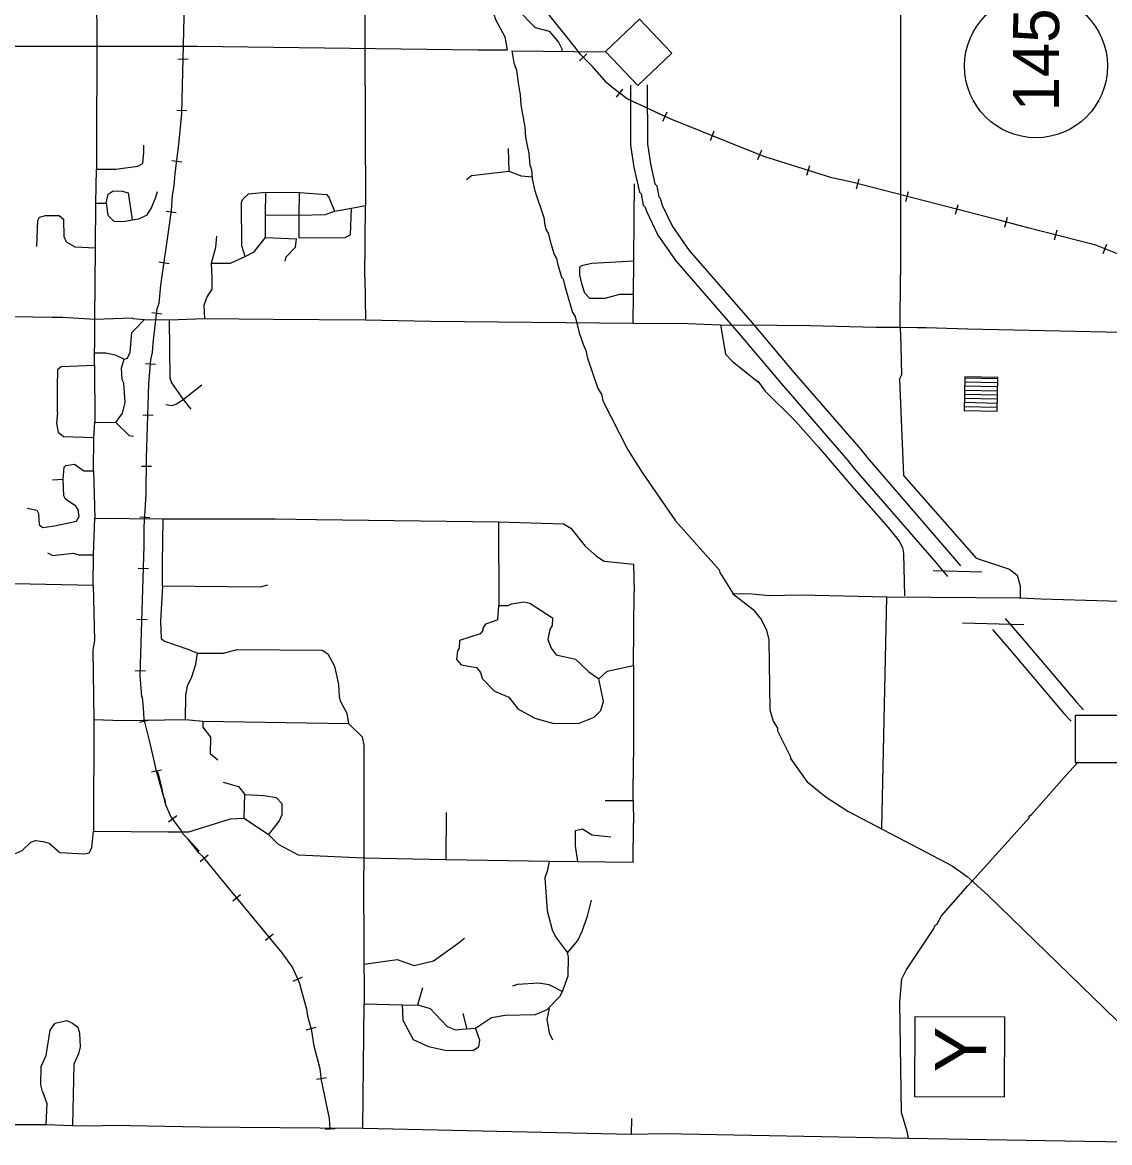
# Model space of a CAD drawing. Extents: x 299354 to 1325680, y 96128 to 228242.
# Drawn here: x 350586 to 371846, y 99941 to 121836 of the extents above; entities that cross this region are included whole.
import ezdxf

# ---------------------------------------------------------------- set-up
doc = ezdxf.new("R2010")
doc.units = 0
for name, color, linetype in [('Level 10', 7, 'Continuous'), ('Level 12', 7, 'Continuous'), ('Level 13', 7, 'Continuous'), ('Level 2', 7, 'Continuous'), ('Level 3', 7, 'Continuous'), ('Level 4', 7, 'Continuous'), ('Level 51', 7, 'Continuous')]:
    doc.layers.add(name, color=color, linetype=linetype)

msp = doc.modelspace()

# ---------------------------------------------------------------- linework, layer by layer
at = {"layer": 'Level 10'}
for p, q in [((368405, 111124), (369350, 111099)), ((368969, 110098), (370168, 110065))]:
    msp.add_line(p, q, dxfattribs=at)
msp.add_lwpolyline([(370086, 110590), (370094, 110590)], dxfattribs=at)
at = {"layer": 'Level 12'}
msp.add_line((370406, 120980), (370406, 120980), dxfattribs=at)
msp.add_circle((370406, 120980), 1398, dxfattribs=at)
at = {"layer": 'Level 13'}
msp.add_line((368892, 101648), (368892, 101648), dxfattribs=at)
msp.add_lwpolyline([(369786, 100826), (368036, 100833), (368042, 102403), (369792, 102396)], close=True, dxfattribs=at)
at = {"layer": 'Level 2'}
for points in [[(367755, 123819), (367758, 116894)], [(359766, 122050), (359807, 122000), (359840, 121891), (360020, 121556), (360068, 121297)], [(329011, 121428), (334049, 121433), (334274, 121464), (334492, 121579), (334660, 121736), (334853, 121834), (334986, 121833), (335377, 121696), (335951, 121566), (336410, 121528), (349544, 121393), (349810, 121323), (350219, 121370), (353997, 121369)], [(353997, 121369), (359492, 121302), (360068, 121297)], [(360159, 121280), (360199, 121046), (360248, 120904), (360279, 120654), (360318, 120420), (360333, 120228), (360412, 119786), (360427, 119586), (360491, 119277), (360506, 119043), (360538, 118960), (360553, 118784), (360601, 118567), (360780, 118024), (360803, 117874), (360819, 117790), (360869, 117715), (360917, 117514), (360982, 117297), (361031, 117222), (361047, 117122), (361128, 116854), (361161, 116821), (361193, 116679), (361346, 116169), (361396, 116085), (361476, 115768), (361557, 115525), (361606, 115425), (361638, 115275), (361841, 114681), (361907, 114572), (361939, 114438), (362423, 113484), (362702, 113040), (363360, 112092), (364211, 111134), (364227, 111084), (364486, 110666)], [(360159, 121280), (361991, 121263)], [(362475, 120612), (362479, 119436), (362545, 119010), (362652, 118516), (362683, 118484), (362723, 118267), (362763, 118227), (362787, 118145), (363011, 117678), (363361, 117173), (364604, 115747), (365429, 114773), (365562, 114621), (366730, 113273), (366846, 113122), (367839, 111976), (368408, 111322), (368675, 111003)], [(362805, 120613), (362809, 119462), (362870, 119070), (362955, 118679), (362990, 118643), (363029, 118426), (363056, 118399), (363096, 118264), (363297, 117844), (363622, 117376), (364855, 115962), (365680, 114988), (365811, 114838), (366986, 113481), (367102, 113330), (368089, 112192), (368659, 111536), (368928, 111215)], [(367749, 115878), (367758, 116894)], [(367749, 115878), (367762, 115519)], [(367762, 115519), (367774, 114944)], [(367739, 114861), (367774, 114944)], [(367739, 114861), (367815, 112981)], [(367815, 112981), (369237, 111362)], [(369237, 111362), (369890, 111150), (370039, 111032), (370096, 110823), (370094, 110590)], [(368400, 111121), (368406, 111114)], [(364473, 110676), (364879, 110362), (365036, 110160), (365134, 109959), (365182, 109767), (365203, 108400), (365268, 108175), (365350, 108041), (365349, 107991), (365603, 107480), (365603, 107447), (365924, 107002), (366305, 106690), (366727, 106420), (368246, 105623), (368769, 105351), (369059, 105140), (369473, 104770), (371977, 102339), (372903, 101480), (373913, 100580), (374045, 100453), (374683, 99957)], [(369806, 110183), (370169, 109764), (371206, 108540), (371335, 108401)], [(369556, 109967), (369918, 109549), (370959, 108321), (371092, 108177)], [(367911, 100026), (367887, 100159), (367774, 100527), (367744, 102686), (367781, 103144), (367866, 103309), (368399, 104113), (368433, 104188), (368467, 104204), (368560, 104370), (369074, 104957), (369142, 105040), (370271, 106288), (370271, 106321), (370321, 106354), (371055, 107189), (371233, 107374)], [(349316, 100294), (351042, 100295)], [(351042, 100295), (351567, 100274)], [(351959, 100270), (352351, 100283)], [(352351, 100283), (354061, 100251)], [(351567, 100274), (351959, 100270)], [(354061, 100251), (356412, 100230)], [(356412, 100230), (357246, 100222)], [(357246, 100222), (362499, 100108)], [(362499, 100108), (363142, 100119)], [(363142, 100119), (367911, 100026)], [(367911, 100026), (371363, 99969)], [(371363, 99969), (373010, 99941)]]:
    msp.add_lwpolyline(points, dxfattribs=at)
for points in [[(361986, 121266), (362622, 120602), (363285, 121238), (362650, 121901)], [(371171, 107371), (372091, 107367), (372094, 108286), (371175, 108290)]]:
    msp.add_lwpolyline(points, close=True, dxfattribs=at)
at = {"layer": 'Level 3'}
for points in [[(362529, 115958), (363596, 115948), (364238, 115926)], [(364238, 115926), (365339, 115916), (365989, 115910)], [(365989, 115910), (367274, 115882)], [(367274, 115882), (367749, 115878)], [(367749, 115878), (368074, 115875)], [(368074, 115875), (368258, 115873)], [(368258, 115873), (369076, 115849)], [(369066, 115849), (372985, 115763)]]:
    msp.add_lwpolyline(points, dxfattribs=at)
at = {"layer": 'Level 4'}
for p, q in [((353628, 121122), (353828, 121117)), ((361483, 121085), (361626, 121225)), ((362204, 120375), (362325, 120534)), ((353603, 120122), (353803, 120117)), ((363109, 119909), (363193, 120090)), ((364040, 119530), (364114, 119715)), ((364968, 119158), (365042, 119344)), ((353505, 119137), (353704, 119112)), ((365927, 118849), (365987, 119040)), ((366896, 118585), (366946, 118779)), ((367864, 118335), (367914, 118529)), ((368833, 118085), (368883, 118279)), ((353398, 118145), (353596, 118118)), ((369800, 117835), (369851, 118028)), ((370770, 117585), (370819, 117779)), ((371717, 117318), (371793, 117503)), ((353257, 117156), (353454, 117127)), ((353114, 116165), (353313, 116141)), ((352992, 115170), (353191, 115154)), ((352941, 114167), (353141, 114161)), ((352912, 113165), (353112, 113163)), ((352880, 112171), (353079, 112159)), ((352852, 111169), (353052, 111163)), ((367393, 106087), (367490, 110611)), ((367490, 110611), (370094, 110590)), ((352823, 110169), (353023, 110163)), ((352794, 109170), (352994, 109164)), ((352879, 108156), (353073, 108204)), ((353108, 107186), (353304, 107228)), ((353443, 106212), (353603, 106332)), ((354062, 105437), (354217, 105564)), ((354699, 104666), (354853, 104793)), ((355337, 103896), (355491, 104024)), ((355884, 103095), (356065, 103180)), ((356136, 102147), (356329, 102200)), ((356334, 101181), (356532, 101210)), ((356504, 100204), (356704, 100219))]:
    msp.add_line(p, q, dxfattribs=at)
for points in [[(357266, 124535), (357296, 118256)], [(359708, 123009), (359945, 122432), (360259, 122096), (360614, 121734), (360888, 121665), (361070, 121447), (361136, 121321), (361135, 121271)], [(352015, 122537), (352041, 121828), (352032, 118970)], [(356604, 100211), (356589, 100411), (356438, 101163), (356406, 101380), (356294, 101823), (356246, 102123), (356166, 102415), (356150, 102549), (356053, 102891), (356013, 103042), (355988, 103109), (355866, 103368), (355668, 103653), (354464, 105106), (354126, 105517), (354043, 105601), (353821, 105878), (353722, 105979), (353705, 106029), (353491, 106315), (353393, 106541), (353353, 106691), (353207, 107201), (353143, 107493), (353063, 107827), (352967, 108219), (352952, 108436), (352937, 108645), (352921, 108653), (352891, 109070), (352915, 109912), (352964, 111603), (352968, 111978), (353007, 112619), (353014, 113319), (353060, 114777), (353098, 115243), (353133, 115385), (353143, 115568), (353224, 116242), (353258, 116350), (353295, 116700), (353331, 116975), (353438, 117699), (353500, 118157), (353520, 118448), (353555, 118648), (353574, 118881), (353646, 119447), (353701, 120055), (353755, 122204)], [(353574, 118881), (353646, 119447), (353701, 120055), (353755, 122204)], [(362411, 120343), (362113, 120570), (362013, 120655), (361725, 120982), (361493, 121218), (361411, 121335), (360801, 122091), (360570, 122359)], [(362591, 120259), (362411, 120343), (362113, 120570), (362013, 120655), (361725, 120982), (361493, 121218), (361411, 121335), (360801, 122091)], [(363254, 119952), (362411, 120343)], [(372032, 117297), (371575, 117485), (370244, 117822), (369686, 117968), (366808, 118711), (366414, 118800), (365086, 119218), (363254, 119952), (362941, 120097)], [(366414, 118800), (365086, 119218), (363254, 119952)], [(352032, 118970), (352415, 118966), (352841, 119029), (352942, 119078), (352960, 119295), (352962, 119437)], [(360083, 119372), (360096, 118930)], [(352025, 118303), (352032, 118970)], [(359269, 118763), (359370, 118845), (360096, 118930)], [(360096, 118930), (360337, 118836), (360554, 118818)], [(353143, 115568), (353224, 116242), (353258, 116350), (353295, 116700), (353331, 116975), (353438, 117699), (353500, 118157), (353520, 118448), (353555, 118648), (353574, 118881)], [(362548, 118008), (362554, 118683)], [(369686, 117968), (366808, 118711), (366414, 118800)], [(352226, 118301), (352261, 118476), (352361, 118542), (352536, 118540), (352653, 118506), (352731, 117980)], [(352731, 117980), (352865, 117996), (353024, 118078), (353109, 118210), (353194, 118418), (353229, 118534)], [(354943, 117260), (354878, 117469), (354870, 118328), (354904, 118386), (355005, 118485), (355347, 118515)], [(355343, 118073), (355347, 118515)], [(355347, 118515), (356006, 118509)], [(356001, 118067), (356006, 118509)], [(356006, 118509), (356531, 118471), (356580, 118420), (356686, 118144)], [(352017, 117428), (352025, 118303)], [(352025, 118303), (352226, 118301)], [(352226, 118301), (352257, 118068), (352373, 117950), (352564, 117948), (352731, 117980)], [(357020, 118208), (357296, 118256)], [(357283, 116856), (357296, 118256)], [(350867, 117455), (350888, 117964), (350922, 118030), (351039, 118062), (351306, 118060), (351389, 117992), (351394, 117651), (351443, 117550), (351609, 117449), (352017, 117428)], [(355339, 117632), (355343, 118073)], [(355343, 118073), (356001, 118067)], [(355997, 117626), (356898, 117634), (356999, 117683), (357020, 118208)], [(355997, 117626), (356001, 118067)], [(356001, 118067), (356510, 118079), (356686, 118144)], [(356686, 118144), (357020, 118208)], [(362540, 117175), (362548, 118008)], [(371575, 117485), (370244, 117822), (369686, 117968)], [(354283, 117133), (354369, 117440), (354388, 117657)], [(354943, 117260), (355119, 117350), (355339, 117632)], [(355339, 117632), (355947, 117609)], [(355726, 117170), (355744, 117253), (355929, 117443), (355947, 117609)], [(352005, 116037), (352017, 117428)], [(375984, 115353), (375410, 115483), (374511, 115666), (374286, 115752), (373838, 115989), (373283, 116386), (372993, 116638), (372604, 116917), (372356, 117119), (372032, 117297), (371575, 117485)], [(354283, 117133), (354658, 117129), (354943, 117260)], [(362534, 116516), (362259, 116519), (361974, 116438), (361683, 116441), (361583, 116542), (361535, 116709), (361487, 116901), (361488, 117051), (361522, 117084), (361722, 117132), (362540, 117175)], [(362534, 116516), (362540, 117175)], [(354156, 116051), (354142, 116309), (354194, 116459), (354295, 116624), (354297, 116833), (354283, 117133)], [(357283, 116856), (357292, 116022)], [(362529, 115958), (362534, 116516)], [(346660, 116152), (351171, 116078), (351371, 116076)], [(351371, 116076), (352005, 116037)], [(352005, 116037), (352730, 116064), (352747, 116047), (352972, 116028)], [(353456, 116024), (354156, 116051)], [(354156, 116051), (355491, 116039)], [(352000, 115578), (352005, 116037)], [(352573, 115257), (352640, 115273), (352691, 115389), (352728, 115772), (352795, 115846), (352972, 116028)], [(352972, 116028), (353456, 116024)], [(353456, 116024), (353470, 114890), (353503, 114790), (353733, 114463)], [(355491, 116039), (357292, 116022)], [(357292, 116022), (358576, 115994)], [(358576, 115994), (362529, 115958)], [(364238, 115926), (364332, 115354), (364472, 115211), (364977, 114807)], [(351999, 115378), (352000, 115578)], [(352968, 111978), (353007, 112619), (353014, 113319), (353060, 114777), (353098, 115243), (353133, 115385), (353143, 115568)], [(351996, 115137), (351999, 115378)], [(351999, 115378), (352215, 115376), (352398, 115341), (352573, 115257)], [(352411, 114016), (352546, 114198), (352598, 114406), (352568, 114782), (352536, 114849), (352521, 115082), (352573, 115257)], [(351275, 114702), (351278, 115060), (351346, 115109), (351996, 115137)], [(351996, 115137), (352003, 114020)], [(353733, 114463), (354094, 114751)], [(364964, 114823), (365112, 114630)], [(351270, 114210), (351275, 114702)], [(365112, 114630), (365699, 114050), (366153, 113537), (366805, 112773), (367424, 112067), (367514, 111966), (367729, 111698), (367794, 111572), (367816, 111454)], [(353390, 114366), (353515, 114348), (353599, 114381), (353733, 114463)], [(353733, 114463), (353882, 114278)], [(351270, 114210), (351252, 113994), (351284, 113827), (351391, 113742), (351983, 113720)], [(351983, 113720), (352003, 114020)], [(352003, 114020), (352411, 114016)], [(352411, 114016), (352676, 113764), (352759, 113747)], [(351977, 113070), (351983, 113720)], [(351384, 112909), (351402, 113142), (351436, 113175), (351603, 113199), (351785, 113072), (351977, 113070)], [(351977, 113070), (352002, 112145)], [(350678, 112340), (350869, 112305), (350902, 112238), (350917, 112013), (350983, 111963), (351217, 111994), (351643, 112090), (351694, 112181), (351678, 112315), (351629, 112382), (351430, 112517), (351397, 112584), (351384, 112909)], [(351175, 112894), (351384, 112909)], [(351979, 111429), (352002, 112145)], [(352002, 112145), (353336, 112133)], [(353324, 110825), (353328, 111266), (353336, 112133)], [(353336, 112133), (355530, 112130)], [(355530, 112130), (356339, 112122)], [(356339, 112122), (359899, 112074)], [(352921, 108653), (352891, 109070), (352915, 109912), (352964, 111603), (352968, 111978)], [(359899, 112074), (359901, 110440)], [(359899, 112074), (361167, 112037), (361308, 111952), (361588, 111600)], [(351078, 111470), (351178, 111419), (351353, 111434), (351587, 111465), (351687, 111431), (351979, 111429)], [(361588, 111600), (361811, 111406)], [(367816, 111454), (367834, 110627)], [(351973, 110837), (351979, 111429)], [(361811, 111406), (361960, 111305), (362535, 111250)], [(362535, 111250), (362547, 110708)], [(349188, 110895), (351973, 110837)], [(351973, 110837), (351997, 109753), (351962, 109570), (351982, 108212)], [(353324, 110825), (353284, 110133), (353298, 109792), (353364, 109741), (353822, 109587), (354013, 109510)], [(353324, 110825), (355242, 110807), (355388, 110842)], [(362534, 109266), (362547, 110708)], [(364483, 110676), (364849, 110670)], [(364849, 110670), (365193, 110634)], [(365190, 110634), (365799, 110645)], [(365799, 110645), (367490, 110611)], [(370094, 110590), (370510, 110569), (371378, 110545)], [(359882, 110157), (359901, 110440)], [(359901, 110440), (360084, 110438), (360151, 110471), (360394, 110511), (360510, 110485), (360949, 110197), (360948, 110047), (360897, 109973), (360862, 109773), (360927, 109606), (361026, 109472), (361401, 109393), (361665, 109141), (361856, 109006)], [(371378, 110545), (372278, 110520)], [(359882, 110157), (359639, 110076), (359588, 109993), (359588, 109951), (359537, 109885), (359136, 109755), (359126, 109605), (359092, 109556), (359074, 109381), (359165, 109280), (359464, 109227), (359547, 109127), (359579, 109010), (359819, 108766), (360101, 108647), (360274, 108420), (360606, 108234), (360980, 108130), (361473, 108142), (361766, 108257), (361900, 108389), (361952, 108563), (361856, 109006)], [(353775, 108212), (353780, 108687), (353815, 108870), (353900, 109044), (353977, 109294), (354013, 109510)], [(354013, 109510), (354521, 109505), (354789, 109578), (356448, 109563), (356556, 109495)], [(356556, 109495), (356687, 109253), (356767, 108893), (356782, 108660), (356798, 108576), (356929, 108334), (356961, 108133)], [(361856, 109006), (362024, 109154), (362534, 109266)], [(362534, 109266), (362534, 107475)], [(354044, 105635), (353821, 105878), (353722, 105979), (353705, 106029), (353491, 106315), (353393, 106541), (353377, 106641), (353353, 106691), (353305, 106916), (353240, 107167), (353207, 107201), (353143, 107493), (353063, 107827), (352967, 108219), (352952, 108436), (352937, 108645), (352921, 108653)], [(351982, 108212), (351979, 106028)], [(351982, 108212), (352541, 108190)], [(352541, 108190), (353775, 108212)], [(353775, 108212), (354117, 108176)], [(354117, 108176), (354116, 108059), (354264, 107866), (354261, 107549), (354410, 107423)], [(354117, 108176), (356961, 108133)], [(356961, 108133), (357233, 107873), (357265, 107706), (357262, 105506)], [(362526, 106625), (362534, 107475)], [(354515, 106989), (354814, 106903), (354938, 106743)], [(354925, 106285), (354938, 106743)], [(354938, 106743), (355305, 106723), (355546, 106688), (355662, 106570), (355660, 106345), (355609, 106229), (355398, 105964)], [(361984, 106629), (362526, 106625)], [(362526, 106625), (362539, 106183)], [(353435, 106015), (353839, 106012), (354658, 106271), (354925, 106285)], [(354925, 106285), (355398, 105964)], [(358871, 105474), (358879, 106391)], [(349314, 105594), (350465, 105600), (350583, 105649), (350751, 105814), (350843, 105847), (350993, 105829), (351109, 105795), (351316, 105609), (351808, 105588), (351892, 105604), (351943, 105704), (351979, 106028)], [(351979, 106028), (353438, 106015)], [(361448, 105434), (361400, 105735), (361403, 106043), (361537, 106075), (361728, 105957), (362094, 105920)], [(362532, 105424), (362539, 106183)], [(355398, 105964), (355588, 105771), (355978, 105567), (357262, 105506)], [(356013, 103042), (355988, 103109), (355866, 103368), (355668, 103653), (354464, 105106), (354126, 105517), (354043, 105601)], [(357262, 105506), (357257, 104997), (357269, 102655)], [(357262, 105506), (358871, 105474)], [(358871, 105474), (360889, 105439)], [(360889, 105439), (360854, 105265), (360802, 105115), (360847, 104473), (360943, 104097), (361009, 103963), (361248, 103653)], [(360889, 105439), (361448, 105434)], [(361448, 105434), (362532, 105424)], [(361248, 103653), (361450, 103893), (361535, 104075), (361638, 104366), (361716, 104682)], [(357265, 103430), (357914, 103517), (358247, 103401), (358628, 103494), (359080, 103820), (359234, 103935)], [(361149, 102895), (361260, 103203), (361264, 103569), (361248, 103653)], [(356604, 100211), (356589, 100411), (356438, 101163), (356406, 101380), (356294, 101823), (356246, 102123), (356166, 102415), (356150, 102549), (356053, 102891), (356013, 103042)], [(358320, 102632), (358417, 102974)], [(360174, 103004), (360275, 103037), (360683, 103066), (360883, 103031), (361149, 102895)], [(359449, 102177), (359760, 102383), (360027, 102430), (360619, 102442), (360845, 102540), (361098, 102796), (361149, 102895)], [(357246, 100222), (357269, 102655)], [(357269, 102655), (358011, 102632)], [(358011, 102632), (358025, 102332), (358230, 101955)], [(358011, 102632), (358336, 102629), (358560, 102560), (358891, 102207), (359057, 102148), (359266, 102162), (359449, 102177)], [(360887, 102564), (360844, 102349), (360889, 102087), (360949, 101952)], [(350981, 100937), (350949, 101071), (350952, 101429), (351054, 101645), (351126, 102136), (351227, 102277), (351453, 102325), (351569, 102274), (351668, 102198), (351701, 102081), (351715, 101814), (351680, 101673), (351595, 101473), (351567, 100274)], [(359285, 102159), (359202, 102461)], [(358230, 101955), (358529, 101819), (358853, 101749), (359395, 101744), (359513, 101810), (359531, 101943), (359449, 102177)], [(350981, 100937), (351062, 100703), (351042, 100295)], [(362499, 100108), (362505, 100409)]]:
    msp.add_lwpolyline(points, dxfattribs=at)
at = {"layer": 'Level 51'}
for p, q in [((369012, 114810), (369657, 114797)), ((369014, 114890), (369659, 114877)), ((369007, 114571), (369652, 114557)), ((369009, 114651), (369654, 114637)), ((369011, 114730), (369655, 114717)), ((369320, 114578), (369320, 114578)), ((369002, 114331), (369647, 114317)), ((369004, 114411), (369649, 114397)), ((369005, 114491), (369650, 114477))]:
    msp.add_line(p, q, dxfattribs=at)
msp.add_lwpolyline([(369014, 114908), (369000, 114251), (369645, 114237), (369659, 114894)], close=True, dxfattribs=at)

# ---------------------------------------------------------------- texts
at = {"layer": 'Level 12'}
msp.add_text('145', height=900, rotation=89.767, dxfattribs=at).set_placement((370853, 120099))
at = {"layer": 'Level 13'}
msp.add_text('Y', height=1000, rotation=89.767, dxfattribs=at).set_placement((369430, 101310))

doc.saveas('drawing.dxf')
